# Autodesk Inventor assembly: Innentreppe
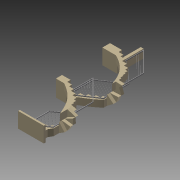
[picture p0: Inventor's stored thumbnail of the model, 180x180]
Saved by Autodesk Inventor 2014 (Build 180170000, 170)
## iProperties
Created: 2013-09
Part Number: Innentreppe
Document SubType Name: Assembly
Designer: Stefan Tammegger
Author: Stefan Tammegger
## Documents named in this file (8)
- Q:\PROJEKTE\INVENTOR\Seemann Alexander\Innengeländer\Innentreppe.iam
- Q:\PROJEKTE\INVENTOR\Seemann Alexander\Innengeländer\Bestand.ipt
- Q:\PROJEKTE\INVENTOR\Seemann Alexander\Innengeländer\Lauf 1.ipt
- Q:\PROJEKTE\INVENTOR\Seemann Alexander\Innengeländer\Lauf 2.ipt
- Q:\PROJEKTE\INVENTOR\Seemann Alexander\Innengeländer\Lauf 3.ipt
- Q:\PROJEKTE\INVENTOR\Seemann Alexander\Innengeländer\Lauf 4.ipt
- C:\Program Files (x86)\Autodesk\Content Service\de-DE\DIN 1587\DIN 1587 - M10 x 1,5.ipt
- C:\Program Files (x86)\Autodesk\Content Service\de-DE\DIN 1587\DIN 1587 - M5 x 0,8.ipt
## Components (85 placed, 7 different names)
1. Bestand:1 — Fluchtend:1, Fluchtend:2, Passend:1, Passend:2, Fluchtend:3, Passend:3, Fluchtend:4, Fluchtend:5, Fluchtend:6, Fluchtend:7, Passend:4, Passend:5, Passend:6, Passend:7, Passend:8, Passend:9, Fluchtend:8, Fluchtend:9, Fluchtend:10, Fluchtend:11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
2. Lauf 1:1 — Fluchtend:1, Fluchtend:2, Passend:1, Passend:2, Fluchtend:3, Passend:3, Fluchtend:4, Fluchtend:5
3. Lauf 2:1 — Fluchtend:6, Fluchtend:7, Passend:4, Passend:5, Passend:6, Passend:7, Passend:8, Passend:9, Fluchtend:8, Fluchtend:9, Fluchtend:10
4. Lauf 3:1 — Fluchtend:11, Fluchtend:12, Fluchtend:13, Passend:10, Passend:11, Passend:12, Passend:13
5. Lauf 4:1 — Fluchtend:14, Fluchtend:15, Fluchtend:16, Passend:14, Passend:15, Passend:16, Fluchtend:17
6. DIN 1587 M10:1
7. DIN 1587 M10:2
8. DIN 1587 M10:3
9. DIN 1587 M10:4
10. DIN 1587 M10:5
11. DIN 1587 M10:6
12. DIN 1587 M10:7
13. DIN 1587 M10:8
14. DIN 1587 M10:9
15. DIN 1587 M10:10
16. DIN 1587 M10:11
17. DIN 1587 M10:12
18. DIN 1587 M10:13
19. DIN 1587 M10:14
20. DIN 1587 M10:15
21. DIN 1587 M10:16
22. DIN 1587 M5:1
23. DIN 1587 M5:2
24. DIN 1587 M5:3
25. DIN 1587 M5:4
26. DIN 1587 M5:5
27. DIN 1587 M5:6
28. DIN 1587 M5:7
29. DIN 1587 M5:8
30. DIN 1587 M5:9
31. DIN 1587 M5:10
32. DIN 1587 M5:11
33. DIN 1587 M5:12
34. DIN 1587 M5:13
35. DIN 1587 M5:14
36. DIN 1587 M5:15
37. DIN 1587 M5:16
38. DIN 1587 M5:17
39. DIN 1587 M5:18
40. DIN 1587 M5:19
41. DIN 1587 M5:20
42. DIN 1587 M5:21
43. DIN 1587 M5:22
44. DIN 1587 M5:23
45. DIN 1587 M5:24
46. DIN 1587 M5:25
47. DIN 1587 M5:26
48. DIN 1587 M5:27
49. DIN 1587 M5:28
50. DIN 1587 M5:29
51. DIN 1587 M5:30
52. DIN 1587 M5:31
53. DIN 1587 M5:32
54. DIN 1587 M5:33
55. DIN 1587 M5:34
56. DIN 1587 M5:35
57. DIN 1587 M5:36
58. DIN 1587 M5:37
59. DIN 1587 M5:38
60. DIN 1587 M5:39
61. DIN 1587 M5:40
62. DIN 1587 M5:41
63. DIN 1587 M5:42
64. DIN 1587 M5:43
65. DIN 1587 M5:44
66. DIN 1587 M5:45
67. DIN 1587 M5:46
68. DIN 1587 M5:47
69. DIN 1587 M5:48
70. DIN 1587 M5:49
71. DIN 1587 M5:50
72. DIN 1587 M5:51
73. DIN 1587 M5:52
74. DIN 1587 M5:53
75. DIN 1587 M5:54
76. DIN 1587 M5:55
77. DIN 1587 M5:56
78. DIN 1587 M5:57
79. DIN 1587 M5:58
80. DIN 1587 M5:59
81. DIN 1587 M5:60
82. DIN 1587 M5:61
83. DIN 1587 M5:62
84. DIN 1587 M5:63
85. DIN 1587 M5:64
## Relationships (33: Flush 17, Mate 16)
- Fluchtend:1 [Flush]: Bestand:1 ↔ Lauf 1:1
- Fluchtend:2 [Flush]: Bestand:1 ↔ Lauf 1:1
- Passend:1 [Mate]: Bestand:1 ↔ Lauf 1:1
- Passend:2 [Mate]: Bestand:1 ↔ Lauf 1:1
- Fluchtend:3 [Flush]: Bestand:1 ↔ Lauf 1:1
- Passend:3 [Mate]: Bestand:1 ↔ Lauf 1:1
- Fluchtend:4 [Flush]: Bestand:1 ↔ Lauf 1:1
- Fluchtend:5 [Flush]: Bestand:1 ↔ Lauf 1:1
- Fluchtend:6 [Flush]: Bestand:1 ↔ Lauf 2:1
- Fluchtend:7 [Flush]: Bestand:1 ↔ Lauf 2:1
- Passend:4 [Mate]: Bestand:1 ↔ Lauf 2:1
- Passend:5 [Mate]: Bestand:1 ↔ Lauf 2:1
- Passend:6 [Mate]: Bestand:1 ↔ Lauf 2:1
- Passend:7 [Mate]: Bestand:1 ↔ Lauf 2:1
- Passend:8 [Mate]: Bestand:1 ↔ Lauf 2:1
- Passend:9 [Mate]: Bestand:1 ↔ Lauf 2:1
- Fluchtend:8 [Flush]: Bestand:1 ↔ Lauf 2:1
- Fluchtend:9 [Flush]: Bestand:1 ↔ Lauf 2:1
- Fluchtend:10 [Flush]: Bestand:1 ↔ Lauf 2:1
- Fluchtend:11 [Flush]: Bestand:1 ↔ Lauf 3:1
- Fluchtend:12 [Flush]: Bestand:1 ↔ Lauf 3:1
- Fluchtend:13 [Flush]: Bestand:1 ↔ Lauf 3:1
- Passend:10 [Mate]: Bestand:1 ↔ Lauf 3:1
- Passend:11 [Mate]: Bestand:1 ↔ Lauf 3:1
- Passend:12 [Mate]: Bestand:1 ↔ Lauf 3:1
- Passend:13 [Mate]: Bestand:1 ↔ Lauf 3:1
- Fluchtend:14 [Flush]: Bestand:1 ↔ Lauf 4:1
- Fluchtend:15 [Flush]: Bestand:1 ↔ Lauf 4:1
- Fluchtend:16 [Flush]: Bestand:1 ↔ Lauf 4:1
- Passend:14 [Mate]: Bestand:1 ↔ Lauf 4:1
- Passend:15 [Mate]: Bestand:1 ↔ Lauf 4:1
- Passend:16 [Mate]: Bestand:1 ↔ Lauf 4:1
- Fluchtend:17 [Flush]: Bestand:1 ↔ Lauf 4:1
